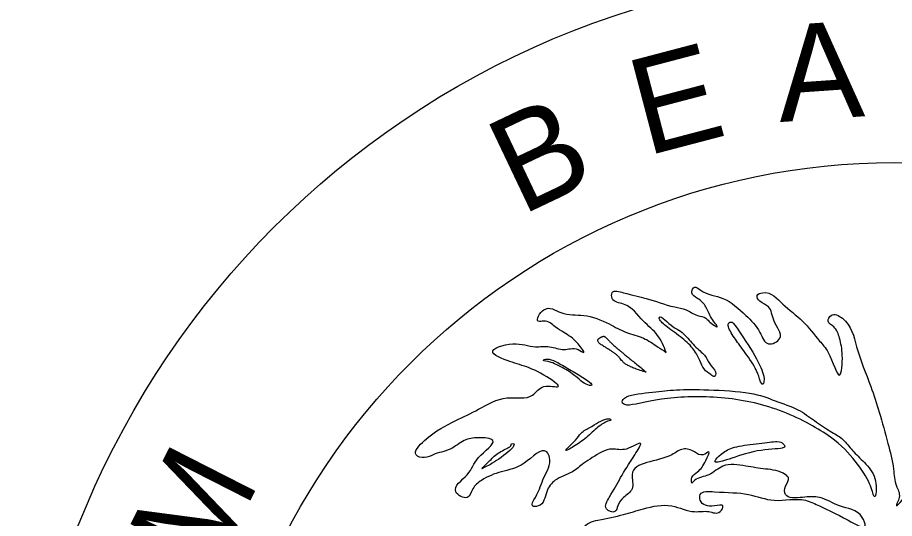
# Model space of a CAD drawing. Extents: x -769.4 to -731.2, y -2181.6 to -2171.
# Drawn here: x -739.7948 to -739.5123, y -2180.9318 to -2180.7705 of the extents above; entities that cross this region are included whole.
import ezdxf

# ---------------------------------------------------------------- set-up
doc = ezdxf.new("R2010")
doc.units = 0
doc.layers.add('Default', color=7, linetype='Continuous')

msp = doc.modelspace()

# ---------------------------------------------------------------- linework, layer by layer
at = {"layer": 'Default'}
for radius in [0.28241, 0.22041]:
    msp.add_circle((-739.51237, -2181.0376), radius, dxfattribs=at)
for points in [[(-739.58585, -2180.87832), (-739.5886, -2180.87282), (-739.59317, -2180.86824), (-739.59958, -2180.86276), (-739.60325, -2180.86091), (-739.60324, -2180.85908), (-739.59958, -2180.8591), (-739.59227, -2180.86092), (-739.5831, -2180.86367), (-739.57945, -2180.86458), (-739.57577, -2180.86641), (-739.57303, -2180.86733), (-739.57212, -2180.86825), (-739.56938, -2180.87008), (-739.5712, -2180.86732), (-739.57303, -2180.86367), (-739.57579, -2180.86091), (-739.57761, -2180.8591), (-739.57669, -2180.85727), (-739.57486, -2180.85817), (-739.56755, -2180.86093), (-739.56021, -2180.86641), (-739.55563, -2180.87191), (-739.55288, -2180.87556), (-739.54923, -2180.87375), (-739.55106, -2180.86824), (-739.55289, -2180.86366), (-739.55563, -2180.86184), (-739.55656, -2180.86), (-739.55472, -2180.85909), (-739.54831, -2180.86274), (-739.54191, -2180.86824), (-739.53642, -2180.87466), (-739.53367, -2180.87831), (-739.53, -2180.88563), (-739.5291, -2180.87923), (-739.53001, -2180.87373), (-739.53185, -2180.87008), (-739.53367, -2180.86824), (-739.53274, -2180.86641), (-739.52909, -2180.86732), (-739.52451, -2180.87648), (-739.51993, -2180.8893), (-739.5172, -2180.89755), (-739.51443, -2180.90761), (-739.51262, -2180.91586), (-739.51169, -2180.92133), (-739.51079, -2180.925), (-739.5117, -2180.92774), (-739.50986, -2180.92592), (-739.50804, -2180.91586), (-739.50621, -2180.90211), (-739.50347, -2180.89297), (-739.50163, -2180.88289), (-739.50072, -2180.87465), (-739.49887, -2180.86642), (-739.49705, -2180.85909), (-739.49797, -2180.85086), (-739.49797, -2180.8472), (-739.49521, -2180.84445), (-739.49522, -2180.84536), (-739.49338, -2180.84903), (-739.49246, -2180.85725), (-739.49156, -2180.86367), (-739.48973, -2180.86551), (-739.48882, -2180.86093), (-739.49156, -2180.85085), (-739.49156, -2180.84627), (-739.4888, -2180.84446), (-739.4879, -2180.84627), (-739.48789, -2180.84993), (-739.48607, -2180.85085), (-739.48697, -2180.84444), (-739.48514, -2180.83987), (-739.48607, -2180.83346), (-739.48697, -2180.83071), (-739.48424, -2180.82889), (-739.4815, -2180.83346), (-739.47781, -2180.84353), (-739.47509, -2180.85178), (-739.47234, -2180.85543), (-739.47233, -2180.85909), (-739.47232, -2180.85269), (-739.47232, -2180.84353), (-739.47232, -2180.83438), (-739.47324, -2180.82979), (-739.47415, -2180.82064)], [(-739.57762, -2180.92043), (-739.57761, -2180.9186), (-739.57577, -2180.91676), (-739.57303, -2180.91311), (-739.57212, -2180.91037), (-739.57396, -2180.91127), (-739.5767, -2180.91037), (-739.58036, -2180.90943), (-739.58403, -2180.91127), (-739.59683, -2180.91768), (-739.59683, -2180.92226), (-739.59959, -2180.92501), (-739.60141, -2180.92775), (-739.60234, -2180.92958), (-739.60508, -2180.92867), (-739.60417, -2180.92501), (-739.6005, -2180.9186), (-739.59593, -2180.91128), (-739.59408, -2180.9076), (-739.59866, -2180.90943), (-739.60324, -2180.90943), (-739.60964, -2180.91219), (-739.6124, -2180.91401), (-739.61605, -2180.91676), (-739.62156, -2180.9195), (-739.6243, -2180.92317), (-739.62704, -2180.92776), (-739.62888, -2180.92775), (-739.62797, -2180.92501), (-739.62521, -2180.91859), (-739.62337, -2180.91219), (-739.6243, -2180.91036), (-739.63162, -2180.91403), (-739.63894, -2180.91676), (-739.64536, -2180.91952), (-739.6481, -2180.92225), (-739.64994, -2180.92501), (-739.65359, -2180.92317), (-739.64993, -2180.91769), (-739.64626, -2180.91219), (-739.6417, -2180.9067), (-739.64627, -2180.90578), (-739.65086, -2180.9067), (-739.65542, -2180.90945), (-739.66093, -2180.91127), (-739.66365, -2180.9122), (-739.66642, -2180.91127), (-739.66367, -2180.9067), (-739.65359, -2180.90028), (-739.64627, -2180.89663), (-739.63712, -2180.89297), (-739.62888, -2180.89205), (-739.6252, -2180.8893), (-739.62063, -2180.8893), (-739.62521, -2180.88564), (-739.63894, -2180.88014), (-739.6417, -2180.87832), (-739.63527, -2180.87556), (-739.62796, -2180.87649), (-739.62338, -2180.87649), (-739.61881, -2180.8774), (-739.61423, -2180.8774), (-739.6124, -2180.87831), (-739.61422, -2180.87557), (-739.6188, -2180.87191), (-739.62156, -2180.87007), (-739.62521, -2180.86824), (-739.62704, -2180.86825), (-739.62522, -2180.86458), (-739.61973, -2180.8655), (-739.61239, -2180.86641), (-739.60416, -2180.86917), (-739.59866, -2180.8719), (-739.59318, -2180.87373), (-739.58859, -2180.87648), (-739.58585, -2180.87832)], [(-739.64169, -2181.00923), (-739.64169, -2181.00557), (-739.64078, -2181.00191), (-739.63986, -2180.99732), (-739.63986, -2180.99182), (-739.63802, -2180.99092), (-739.63803, -2180.99183), (-739.63346, -2180.98909), (-739.63161, -2180.99001), (-739.63163, -2180.99276), (-739.63071, -2180.99366), (-739.62979, -2180.99274), (-739.62979, -2180.99183), (-739.6243, -2180.9781), (-739.62522, -2180.97901), (-739.62795, -2180.98177), (-739.63071, -2180.9845), (-739.63345, -2180.98726), (-739.63529, -2180.98908), (-739.63804, -2180.98909), (-739.63804, -2180.98451), (-739.6371, -2180.98085), (-739.63711, -2180.97811), (-739.64078, -2180.97903), (-739.64443, -2180.98175), (-739.6481, -2180.98267), (-739.65175, -2180.98543), (-739.65267, -2180.98542), (-739.65542, -2180.98635), (-739.65817, -2180.98725), (-739.66, -2180.98726), (-739.65909, -2180.9836), (-739.65359, -2180.97809), (-739.64901, -2180.9726), (-739.64627, -2180.96987), (-739.64443, -2180.96802), (-739.64809, -2180.96803), (-739.65176, -2180.96803), (-739.65177, -2180.97078), (-739.65541, -2180.9717), (-739.65633, -2180.97169), (-739.65725, -2180.96803), (-739.64902, -2180.96161), (-739.64078, -2180.95614), (-739.63438, -2180.95246), (-739.63163, -2180.95156), (-739.62978, -2180.9488), (-739.63161, -2180.94882), (-739.63527, -2180.9488), (-739.6362, -2180.94699), (-739.63436, -2180.94423), (-739.62613, -2180.94239), (-739.61971, -2180.93965), (-739.61332, -2180.93875), (-739.60691, -2180.93782), (-739.60873, -2180.93691), (-739.6124, -2180.9369), (-739.61239, -2180.93507), (-739.60782, -2180.93232), (-739.59957, -2180.93051), (-739.59318, -2180.92866), (-739.58402, -2180.92775), (-739.5767, -2180.92959), (-739.57213, -2180.92959), (-739.56846, -2180.92959), (-739.56754, -2180.92776), (-739.57029, -2180.92775), (-739.57485, -2180.92592), (-739.57487, -2180.92408), (-739.57029, -2180.92317), (-739.5593, -2180.92409), (-739.55105, -2180.92592), (-739.54098, -2180.92592), (-739.53641, -2180.92775), (-739.52726, -2180.93233), (-739.52177, -2180.93417), (-739.52268, -2180.93142), (-739.53, -2180.92774), (-739.53642, -2180.92501), (-739.54191, -2180.925), (-739.5474, -2180.92408), (-739.54739, -2180.92134), (-739.54648, -2180.9186), (-739.54739, -2180.91768), (-739.55382, -2180.91586), (-739.56022, -2180.91493), (-739.56754, -2180.91494), (-739.57211, -2180.91769), (-739.5767, -2180.91952), (-739.57762, -2180.92043)]]:
    msp.add_spline(points, degree=3, dxfattribs=at)
for points, degree in [([(-739.57028, -2180.88609), (-739.56998, -2180.88594), (-739.56936, -2180.88472), (-739.57212, -2180.88199), (-739.57304, -2180.87924), (-739.57669, -2180.87649), (-739.58035, -2180.8719), (-739.58218, -2180.871), (-739.58494, -2180.86915), (-739.58767, -2180.86641), (-739.58859, -2180.86733), (-739.58586, -2180.87009), (-739.58036, -2180.87373), (-739.57669, -2180.87741), (-739.57486, -2180.88106), (-739.57396, -2180.88381), (-739.5712, -2180.88563), (-739.57059, -2180.88624), (-739.57028, -2180.88609)], 3), ([(-739.56495, -2180.86855), (-739.5654, -2180.86855), (-739.56663, -2180.86915), (-739.56388, -2180.87374), (-739.56113, -2180.8774), (-739.55656, -2180.8838), (-739.55564, -2180.88747), (-739.55471, -2180.88931), (-739.55381, -2180.88656), (-739.55654, -2180.88014), (-739.56388, -2180.86917), (-739.56449, -2180.86855), (-739.56495, -2180.86855)], 3), ([(-739.59225, -2180.88472), (-739.59774, -2180.88014), (-739.60232, -2180.87648), (-739.60508, -2180.87374), (-739.60599, -2180.87282), (-739.60874, -2180.87466), (-739.60416, -2180.87741), (-739.60142, -2180.87923), (-739.59867, -2180.88288), (-739.59225, -2180.88472)], 2), ([(-739.61011, -2180.889), (-739.60965, -2180.889), (-739.60966, -2180.88839), (-739.6124, -2180.88655), (-739.61698, -2180.8838), (-739.62155, -2180.88105), (-739.62429, -2180.88015), (-739.62612, -2180.88105), (-739.62338, -2180.88107), (-739.6179, -2180.88382), (-739.61423, -2180.88656), (-739.61241, -2180.88838), (-739.61056, -2180.889), (-739.61011, -2180.889)], 3), ([(-739.51903, -2180.92424), (-739.51872, -2180.92501), (-739.51811, -2180.92501), (-739.5181, -2180.91768), (-739.52268, -2180.91311), (-739.52634, -2180.90945), (-739.52909, -2180.90577), (-739.53275, -2180.90395), (-739.53824, -2180.90028), (-739.54283, -2180.89662), (-739.55105, -2180.89388), (-739.55747, -2180.89112), (-739.57303, -2180.89022), (-739.5831, -2180.89022), (-739.58951, -2180.89112), (-739.6005, -2180.89205), (-739.6005, -2180.89663), (-739.5886, -2180.89296), (-739.56937, -2180.89205), (-739.55015, -2180.89571), (-739.53275, -2180.90486), (-739.52542, -2180.91218), (-739.51994, -2180.92042), (-739.51933, -2180.92348), (-739.51903, -2180.92424)], 3), ([(-739.6037, -2180.90013), (-739.60355, -2180.89998), (-739.60415, -2180.89938), (-739.6069, -2180.90028), (-739.60966, -2180.90212), (-739.61331, -2180.90396), (-739.61423, -2180.90578), (-739.61697, -2180.90852), (-739.61881, -2180.91036), (-739.61697, -2180.90943), (-739.61241, -2180.90669), (-739.60873, -2180.90304), (-739.60507, -2180.90029), (-739.60385, -2180.90028), (-739.6037, -2180.90013)], 3), ([(-739.54816, -2180.90776), (-739.54862, -2180.9073), (-739.54924, -2180.9067), (-739.55563, -2180.90761), (-739.56387, -2180.90853), (-739.56754, -2180.91037), (-739.57028, -2180.9131), (-739.57029, -2180.91401), (-739.56662, -2180.91309), (-739.55655, -2180.90944), (-739.54648, -2180.90944), (-739.5477, -2180.90821), (-739.54816, -2180.90776)], 3), ([(-739.63558, -2180.90777), (-739.63589, -2180.90792), (-739.63528, -2180.90852), (-739.63987, -2180.91035), (-739.6426, -2180.9131), (-739.64536, -2180.91586), (-739.64536, -2180.91586), (-739.63986, -2180.91309), (-739.63344, -2180.90761), (-739.63527, -2180.90762), (-739.63558, -2180.90777)], 3)]:
    msp.add_open_spline(points, degree=degree, dxfattribs=at)

# ---------------------------------------------------------------- texts
for s, rotation, p in [('A', 3.9657, (-739.54923, -2180.80417)), ('E', 14.7047, (-739.59227, -2180.81515)), ('B', 25.4436, (-739.63253, -2180.83438)), ('M', 63.0299, (-739.73232, -2180.95065))]:
    msp.add_text(s, height=0.031, rotation=rotation, dxfattribs=at).set_placement(p)

doc.saveas('drawing.dxf')
